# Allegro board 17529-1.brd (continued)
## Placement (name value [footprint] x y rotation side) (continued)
L2102  HCB1608KF-601T10-GP  [L603H38]  191.39 122.81 90 top
L2701  MHC1608S800QBP-GP  [L603H38]  76.33 232.16 90 top
L2702  MHC1608S800QBP-GP  [L603H38]  54.36 225.55 90 top
L2703  MHC1608S800QBP-GP  [L603H38]  54.36 224.28 90 top
L3001  MCB1005S121FBP-GP  [L402H24]  8.95 22.73 270 top
L3002  MCB1005S121FBP-GP  [L402H24]  9.03 25.35 270 top
L3003  MCB1005S121FBP-GP  [L402H24]  18.35 18.29 270 top
L3004  MCB1005S121FBP-GP  [L402H24]  18.41 21.34 270 top
L3005  MCB1005S121FBP-GP  [L402H24]  16 30.2 0 top
L3006  MCB1005S121FBP-GP  [L402H24]  14.99 30.2 0 top
L5301  IND-100UH-40-GP  [L6060-6018H186]  197.31 8.41 0 top
L5901  MHC1608S600QBP-GP  [L603H38]  67.39 27.25 0 top
L5902  MHC1608S600QBP-GP  [L603H38]  55.5 17.65 0 top
L5903  BLM18BB470SN1D-GP  [L1608-UH38]  65.1 15.37 0 top
L5904  BLM18BB470SN1D-GP  [L1608-UH38]  62.79 15.49 0 top
L5905  BLM18BB470SN1D-GP  [L1608-UH38]  60.58 15.49 0 top
L9501  MHC1608S601LBP-GP  [L603H38]  203.66 44.53 270 top
L9502  MHC1608S601LBP-GP  [L603H38]  190.6 58.9 0 top
L9503  MHC1608S601LBP-GP  [L603H38]  193.17 69.7 270 top
L9504  MHC1608S601LBP-GP  [L603H38]  192.43 67.72 0 top
LED1  LED-W-130-GP  [LED3640AK-1H160]  27.14 247.83 90 top
LPC1  ACES-CON14-5-GP  [87212-1400N]  228.02 99.49 180 top
NGFF1  SKT-NGFF75P-91-GP  [AS0BC21-S40BE-7H]  207 197 90 top
NGFF2  SKT-NGFF75P-90-GP-U  [AS0BC21-S85BM-7H]  144.86 130.9 0 top
NOREF  *  [unnamed]  46.41 22.81 0 top
NOREF#2  *  [unnamed]  234.7 183.44 0 top
NOREF#3  *  [unnamed]  119.58 67.16 0 top
NOREF#4  -  [#2]  0 253.23 0 top
NOREF#5  -  [#2]  6.2 268.6 180 top
NOREF#6  -  [#2]  173.48 143.38 0 top
NOREF#7  -  [unnamed]  11.58 254.45 0 top
NOREF#8  *  [unnamed]  146.1 95.15 0 top
NOREF#9  -  [unnamed]  116.41 149.38 0 top
NOREF#10  -  [#2]  174.02 160.27 0 top
NOREF#11  -  [unnamed]  144.86 103.3 0 top
NOREF#12  -  [unnamed]  230.38 3.81 0 top
NOREF#13  -  [unnamed]  41.41 74.38 0 top
NOREF#14  *  [unnamed]  238.3 3.2 0 top
NOREF#15  -  [#2]  237.8 224.8 0 top
NOREF#16  *  [unnamed]  238.63 226.95 0 top
NOREF#17  -  [unnamed]  241.05 229.62 0 top
NOREF#18  -  [unnamed]  41.41 149.38 0 top
NOREF#19  -  [#2]  -45.72 10.16 0 top
NOREF#20  -  [#2]  0 0 0 top
NOREF#21  *  [unnamed]  28.45 131.01 0 top
NOREF#22  -  [#2]  173.86 137.16 0 top
NOREF#23  *  [unnamed]  17.91 246 0 top
NOREF#24  -  [unnamed]  116.41 74.38 0 top
NOREF#25  -  [unnamed]  144.86 53.3 0 top
NOREF#26  *  [unnamed]  112.19 30.45 0 top
NOREF#27  -  [unnamed]  240.3 251.83 0 top
NOREF#28  -  [unnamed]  232.42 238.95 0 top
NOREF#29  -  [#2]  0 0 0 top
NOREF#30  -  [unnamed]  3.7 241.57 0 top
NOREF#31  -  [unnamed]  21.59 247.01 0 top
NOREF#32  -  [#2]  9.91 146.86 0 top
NOREF#33  -  [#2]  244 0 90 top
NOREF#34  *  [unnamed]  238.63 226.95 180 bottom
NOREF#35  *  [unnamed]  17.91 246 180 bottom
NOREF#36  *  [unnamed]  238.3 3.2 180 bottom
PC1034  SC22U6D3V5MX-2DLGP  [C805H54]  70.61 114.43 90 top
PC1035  SC47U6D3V5MX-1DL-GP  [C805H54]  38.73 90.93 180 top
PC1036  SC22U6D3V5MX-2DLGP  [C805H54]  69.77 108.1 180 top
PC1037  SC22U6D3V5MX-2DLGP  [C805H54]  71.94 108.1 180 top
PC1038  SC22U6D3V5MX-2DLGP  [C805H54]  71.94 111.68 180 top
PC1039  SC22U6D3V5MX-2DLGP  [C805H54]  74.1 111.68 180 top
PC1040  SC22U6D3V5MX-2DLGP  [C805H54]  69.77 111.68 180 top
PC1041  SC47U6D3V5MX-1DL-GP  [C805H54]  38.68 99.01 180 top
PC1042  SC47U6D3V5MX-1DL-GP  [C805H54]  38.71 106.91 180 top
PC1043  SC47U6D3V5MX-1DL-GP  [C805H54]  38.61 83.19 0 top
PC1044  SC47U6D3V5MX-1DL-GP  [C805H54]  31.67 118.47 180 top
PC1045  SC47U6D3V5MX-1DL-GP  [C805H54]  33.66 118.47 180 top
PC1046  SC22U6D3V3MX-1-DL-GP  [C603H40]  86.41 109.14 270 top
PC1047  SC22U6D3V3MX-1-DL-GP  [C603H40]  74.14 115.01 0 top
PC1048  SC22U6D3V3MX-1-DL-GP  [C603H40]  72.97 115.01 0 top
PC1049  SC22U6D3V3MX-1-DL-GP  [C603H40]  83.59 116.15 0 top
PC1050  SC47U6D3V5MX-1DL-GP  [C805H54]  85.98 116.51 270 top
PC1051  SC47U6D3V5MX-1DL-GP  [C805H54]  85.98 114.58 270 top
PC1052  SC47U6D3V5MX-1DL-GP  [C805H54]  85.98 112.65 270 top
PC1053  SC47U6D3V5MX-1DL-GP  [C805H54]  85.98 110.72 270 top
PC1068  SC22U6D3V5MX-2DLGP  [C805H54]  70.61 116.51 90 top
PC4401  SC1U50V3KX-1-GP  [C603H36]  24.31 80.39 180 top
PC4402  SC2D2U10V3KX-1DLGP-U  [C603H36]  20.83 76.71 270 top
PC4403  SCD01U50V2KX-1DLGP  [C402H22]  18.54 78.49 180 top
PC4404  SC470P50V2KX-3DLGP  [C402H22]  29.03 72.47 270 top
PC4405  SC2200P50V2KX-2DLGP  [C402H22]  28.88 70.54 270 top
PC4406  SC33P50V2JN-3DLGP  [C402H22]  27.46 71.07 0 top
PC4407  SCD1U25V2KX-1-DL-GP  [C402H22]  24.77 60.33 0 top
PC4408  SCD1U25V2KX-1-DL-GP  [C402H22]  25.98 62.23 0 top
PC4409  SC1KP50V2KX-1DLGP  [C402H22]  29.46 75.82 180 top
PC4410  SCD1U25V2KX-1-DL-GP  [C402H22]  26.62 64.26 0 top
PC4411  SC3300P50V2KX-1DLGP  [C402H22]  27.51 75.82 0 top
PC4412  SCD1U25V2KX-1-DL-GP  [C402H22]  26.09 66.17 0 top
PC4413  SC220P50V2KX-3DLGP  [C402H22]  27.43 69.14 0 top
PC4414  SC470P50V2KX-3DLGP  [C402H22]  25.53 76.33 180 top
PC4415  SC1500P50V2KX-2-DL-GP  [C402H22]  28.32 69.14 0 top
PC4416  SC1KP50V2KX-1DLGP  [C402H22]  26.8 67.56 90 top
PC4417  SC470P50V2KX-3DLGP  [C402H22]  8.81 73.15 0 top
PC4418  SC2200P50V2KX-2DLGP  [C402H22]  12.57 71.09 90 top
PC4419  SC33P50V2JN-3DLGP  [C402H22]  12.57 72.01 90 top
PC4420  SCD1U25V2KX-1-DL-GP  [C402H22]  14.15 66.04 0 top
PC4421  SCD1U25V2KX-1-DL-GP  [C402H22]  12.95 63.5 0 top
PC4422  SC1KP50V2KX-1DLGP  [C402H22]  12.19 76.07 180 top
PC4423  SC3300P50V2KX-1DLGP  [C402H22]  14.22 76.07 0 top
PC4424  SC220P50V2KX-3DLGP  [C402H22]  11.94 69.7 0 top
PC4425  SC1500P50V2KX-2-DL-GP  [C402H22]  12.83 69.7 0 top
PC4426  SC470P50V2KX-3DLGP  [C402H22]  16.26 76.07 180 top
PC4427  SC1KP50V2KX-1DLGP  [C402H22]  13.46 68.2 270 top
PC4428  SCD1U25V2KX-1-DL-GP  [C402H22]  15.16 62.46 0 top
PC4429  SCD1U25V2KX-1-DL-GP  [C402H22]  22.23 60.33 0 top
PC4501  SC10U25V5KX-DL-GP  [C805H58]  51.51 46.08 180 top
PC4502  SC10U25V5KX-DL-GP  [C805H58]  53.54 46.08 180 top
PC4503  SCD1U50V3KX-DL-GP  [C603H35]  40.23 50.62 90 top
PC4504  SC1U50V3KX-1-GP  [C603H36]  38.48 45.29 270 top
PC4505  SC1500P50V2KX-2-DL-GP  [C402H22]  33.22 64.87 270 top
PC4506  SC10U25V5KX-DL-GP  [C805H58]  60.2 49.02 270 top
PC4507  SC10U25V5KX-DL-GP  [C805H58]  70.48 50.93 180 top
PC4508  SCD1U50V3KX-DL-GP  [C603H35]  58.55 55.27 90 top
PC4509  SC1U50V3KX-1-GP  [C603H36]  56.26 50.29 270 top
PC4510  SC1500P50V2KX-2-DL-GP  [C402H22]  53.34 69.6 270 top
PC4511  SC10U25V5KX-DL-GP  [C805H58]  79.45 51.97 180 top
PC4512  SC10U25V5KX-DL-GP  [C805H58]  88.52 51.69 180 top
PC4513  SCD1U50V3KX-DL-GP  [C603H35]  76.83 58.29 90 top
PC4514  SC1U50V3KX-1-GP  [C603H36]  74.88 53.06 270 top
PC4515  SC1500P50V2KX-2-DL-GP  [C402H22]  71.63 72.64 270 top
PC4516  SC10U25V5KX-DL-GP  [C805H58]  105.28 51.69 90 top
PC4517  SC10U25V5KX-DL-GP  [C805H58]  97.94 52.22 180 top
PC4518  SCD1U50V3KX-DL-GP  [C603H35]  95.38 58.8 90 top
PC4519  SC1U50V3KX-1-GP  [C603H36]  93.85 52.96 270 top
PC4520  SC1500P50V2KX-2-DL-GP  [C402H22]  90.17 73.15 270 top
PC4601  SC10U25V5KX-DL-GP  [C805H58]  11.43 89.15 90 top
PC4602  SC10U25V5KX-DL-GP  [C805H58]  11.43 91.19 90 top
PC4603  SCD1U50V3KX-DL-GP  [C603H35]  13.84 87.38 90 top
PC4604  SC1U50V3KX-1-GP  [C603H36]  12.32 82.04 270 top
PC4605  SC1500P50V2KX-2-DL-GP  [C402H22]  16.26 85.47 0 top
PC4606  SC10U25V5KX-DL-GP  [C805H58]  12.19 116.2 90 top
PC4607  SC10U25V5KX-DL-GP  [C805H58]  12.19 118.24 90 top
PC4608  SCD1U50V3KX-DL-GP  [C603H35]  15.88 128.57 90 top
PC4609  SC1U50V3KX-1-GP  [C603H36]  19 124.74 0 top
PC4610  SC1500P50V2KX-2-DL-GP  [C402H22]  26.57 122.48 180 top
PC4701  SC1U50V3KX-1-GP  [C603H36]  116.28 40.36 90 top
PC4702  SC10U25V5KX-DL-GP  [C805H58]  113.97 39.5 0 top
PC4703  SC10U25V5KX-DL-GP  [C805H58]  112.04 39.5 0 top
PC4704  SCD1U50V3KX-DL-GP  [C603H35]  118.95 38.53 270 top
PC4705  SC1U50V3KX-1-GP  [C603H36]  125.09 55.75 90 top
PC4706  SC1U50V3KX-1-GP  [C603H36]  122.05 37.97 90 top
PC4707  SC1500P50V2KX-2-DL-GP  [C402H22]  124.71 46.08 0 top
PC4708  SC18P50V2JN-1DLGP  [C402H22]  123.57 33.4 0 top
PC4801  SC10U10V5KX-2DLGP  [C805H50]  127 104.01 270 top
PC4802  SC10U10V5KX-2DLGP  [C805H50]  127 101.98 270 top
PC4803  SCD1U16V2KX-3DLGP  [C402H22]  126.36 105.54 270 top
PC4804  SC1U50V3KX-1-GP  [C603H36]  127.99 90.73 270 top
PC4805  SCD047U25V2KX-4-GP  [C402H22]  131.57 93.34 180 top
PC4806  SCD01U50V2KX-1DLGP  [C402H22]  127.74 91.87 270 top
PC4807  SC1KP50V2KX-1DLGP  [C402H22]  134.54 91.67 180 top
PC4808  SC22U6D3V5MX-2DLGP  [C805H54]  123.9 99.97 180 top
PC4809  SC22U6D3V5MX-2DLGP  [C805H54]  121.87 100 180 top
PC4810  SCD1U16V2KX-3DLGP  [C402H22]  120.4 100.2 180 top
PC4811  SCD047U25V2KX-4-GP  [C402H22]  135.51 93.6 0 top
PC4812  SC2200P50V2KX-2DLGP  [C402H22]  136.53 92.58 180 top
PC4901  SC10U25V5KX-DL-GP  [C805H58]  39.07 207.21 180 top
PC4902  SC10U25V5KX-DL-GP  [C805H58]  53.21 208.28 0 top
PC4903  SC10U25V5KX-DL-GP  [C805H58]  41.15 201.68 0 top
PC4904  SC10U25V5KX-DL-GP  [C805H58]  51.18 208.28 0 top
PC4905  SC10U25V5KX-DL-GP  [C805H58]  39.12 201.68 0 top
PC4906  SCD1U50V3KX-DL-GP  [C603H35]  33.66 195.83 90 top
PC4907  SCD1U50V3KX-DL-GP  [C603H35]  37.64 191.74 90 top
PC4908  SCD1U50V3KX-DL-GP  [C603H35]  26.97 191.64 90 top
PC4909  SC1U50V3KX-1-GP  [C603H36]  80.64 216.28 180 top
PC4910  SC1U50V3KX-1-GP  [C603H36]  16.51 207.52 180 top
PC4911  SC1KP50V2KX-1DLGP  [C402H22]  56.26 207.65 270 top
PC4912  SC1KP50V2KX-1DLGP  [C402H22]  36.32 206.88 90 top
PC4913  SCD1U16V2KX-3DLGP  [C402H22]  29.51 196.24 180 top
PC4914  SC22P50V2JN-4DLGP  [C402H22]  33.73 186.36 180 top
PC4915  SC22P50V2JN-4DLGP  [C402H22]  28.45 186.44 180 top
PC4916  SC1U50V3KX-1-GP  [C603H36]  31.57 186.49 0 top
PC4917  SC1U50V3KX-1-GP  [C603H36]  31.55 196.65 180 top
PC4918  SCD22U10V2KX-2-GP  [C402H22]  36.58 189.61 90 top
PC4919  SCD22U10V2KX-2-GP  [C402H22]  27.48 190.58 270 top
PC5001  SC1U50V3KX-1-GP  [C603H36]  55.04 189.31 90 top
PC5002  SC1U50V3KX-1-GP  [C603H36]  55.04 190.58 90 top
PC5003  SC1U50V3KX-1-GP  [C603H36]  63.63 193.68 0 top
PC5004  SC10U25V5KX-DL-GP  [C805H58]  59.94 193.42 0 top
PC5005  SC10U25V5KX-DL-GP  [C805H58]  61.98 198.12 180 top
PC5006  SC10U25V5KX-DL-GP  [C805H58]  61.98 193.42 0 top
PC5007  SC10U25V5KX-DL-GP  [C805H58]  59.94 198.12 180 top
PC5008  SCD1U50V3KX-DL-GP  [C603H35]  52.58 195.96 0 top
PC5009  SC10U10V5KX-2DLGP  [C805H50]  48.9 196.6 180 top
PC5010  SC1U50V3KX-1-GP  [C603H36]  92.38 191.11 90 top
PC5011  SC10U10V5KX-2DLGP  [C805H50]  44.32 191.39 270 top
PC5012  SC10U10V5KX-2DLGP  [C805H50]  44.32 193.32 270 top
PC5013  SC18P50V2JN-1DLGP  [C402H22]  46.86 188.59 0 top
PC5014  SC1500P50V2KX-2-DL-GP  [C402H22]  65.89 192.63 270 top
PC5015  SCD047U25V2KX-4-GP  [C402H22]  44.45 189.99 270 top
PC5101  SC1U50V3KX-1-GP  [C603H36]  234.59 145.69 270 top
PC5102  SC10U25V5KX-DL-GP  [C805H58]  234.16 144.15 270 top
PC5103  SC10U25V5KX-DL-GP  [C805H58]  237.69 137.77 90 top
PC5104  SC10U25V5KX-DL-GP  [C805H58]  237.69 135.84 90 top
PC5105  SC10U25V5KX-DL-GP  [C805H58]  234.16 142.19 270 top
PC5106  SCD1U50V3KX-DL-GP  [C603H35]  234.45 147.64 90 top
PC5107  SC1U50V3KX-1-GP  [C603H36]  225.32 128.14 180 top
PC5108  SC18P50V2JN-1DLGP  [C402H22]  230.89 154.05 90 top
PC5109  SC1U50V3KX-1-GP  [C603H36]  230.59 149.07 270 top
PC5110  SC1500P50V2KX-2-DL-GP  [C402H22]  227.48 143.21 0 top
PC5201  SC10U10V5KX-2DLGP  [C805H50]  150.04 194.51 90 top
PC5202  SC1U50V3KX-1-GP  [C603H36]  143.26 191.9 180 top
PC5203  SC10U10V5KX-2DLGP  [C805H50]  154.94 193.55 180 top
PC5204  SC10U10V5KX-2DLGP  [C805H50]  152.91 193.55 180 top
PC5205  SCD1U16V2KX-3DLGP  [C402H22]  143 187.83 270 top
PC5206  SC150P50V2JN-3GP  [C402H22]  152.65 189.23 180 top
PG4501  GAP-CLOSE-PWR-3-GP  [GAP-CLOSE-PWR-3]  45.59 58.17 90 bottom
PG4502  GAP-CLOSE-PWR-3-GP  [GAP-CLOSE-PWR-3]  44.55 60.17 180 bottom
PG4503  GAP-CLOSE-PWR-3-GP  [GAP-CLOSE-PWR-3]  56.64 64.9 135 bottom
PG4504  GAP-CLOSE-PWR-3-GP  [GAP-CLOSE-PWR-3]  57.4 65.66 135 bottom
PG4505  GAP-CLOSE-PWR-3-GP  [GAP-CLOSE-PWR-3]  76.83 67.82 135 bottom
PG4506  GAP-CLOSE-PWR-3-GP  [GAP-CLOSE-PWR-3]  77.6 68.58 135 bottom
PG4507  GAP-CLOSE-PWR-3-GP  [GAP-CLOSE-PWR-3]  100.58 66.17 90 bottom
PG4508  GAP-CLOSE-PWR-3-GP  [GAP-CLOSE-PWR-3]  99.14 68.17 180 bottom
PG4601  GAP-CLOSE-PWR-3-GP  [GAP-CLOSE-PWR-3]  23.67 94.82 0 bottom
PG4602  GAP-CLOSE-PWR-3-GP  [GAP-CLOSE-PWR-3]  24.89 97.28 180 bottom
PG4603  GAP-CLOSE-PWR-3-GP  [GAP-CLOSE-PWR-3]  23.55 109.17 0 bottom
PG4604  GAP-CLOSE-PWR-3-GP  [GAP-CLOSE-PWR-3]  25.15 110.46 180 bottom
PG4701  GAP-CLOSE-PWR-3-GP  [GAP-CLOSE-PWR-3]  124.33 54.36 270 top
PG4901  GAP-CLOSE-PWR-3-GP  [GAP-CLOSE-PWR-3]  16.51 193.8 90 top
PG4902  GAP-CLOSE-PWR-3-GP  [GAP-CLOSE-PWR-3]  83.69 204.34 90 top
PG4903  GAP-CLOSE-PWR-2U-GP  [GAP-CLOSE-PWR-2U]  30.45 196.24 90 top
PG5005  GAP-CLOSE-PWR-3-GP  [GAP-CLOSE-PWR-3]  43.94 194.94 0 top
PG5006  GAP-CLOSE-PWR-3-GP  [GAP-CLOSE-PWR-3]  43.94 195.71 0 top
PL4501  COIL-D36UH-19-GP  [RT-D6D3-1D4-103065H394]  46.23 58.8 270 top
PL4502  COIL-D36UH-19-GP  [RT-D6D3-1D4-103065H394]  64.52 63.5 270 top
PL4503  COIL-D36UH-19-GP  [RT-D6D3-1D4-103065H394]  82.8 66.55 270 top
PL4504  COIL-D36UH-19-GP  [RT-D6D3-1D4-103065H394]  101.35 67.06 270 top
PL4601  COIL-D36UH-19-GP  [RT-D6D3-1D4-103065H394]  24.26 96.65 180 top
PL4602  COIL-D36UH-19-GP  [RT-D6D3-1D4-103065H394]  24.26 110.87 180 top
PL4701  IND-D47UH-22-GP-U  [L7066-1830-UH119]  119.76 51.82 180 top
PL4901  IND-2D2UH-356-GP  [RT-D6D6-6D6-108108H426]  68.96 209.17 180 top
PL4902  IND-2D2UH-356-GP  [RT-D6D6-6D6-108108H426]  23.52 207.54 180 top
PL4903  MHC2012S800UBP-GP  [L805H44]  50.42 213.82 0 top
PL4904  MHC2012S800UBP-GP  [L805H44]  47.19 213.84 0 top
PL4905  MHC2012S800UBP-GP  [L805H44]  44.27 213.89 0 top
PL5001  COIL-1D2UH-50-GP  [RT-D6D4-1D9-103072H394]  78.59 195.12 180 top
PL5002  MHC2012S800UBP-GP  [L805H44]  57.18 197.26 270 top
PL5003  MHC2012S800UBP-GP  [L805H44]  57.18 195.3 270 top
PL5101  IND-1D5UH-52-GP  [L115100-2030H158]  231.55 128.14 0 top
PL5104  MHC2012S800UBP-GP  [L805H44]  237.72 145.47 90 top
PL5105  MHC2012S800UBP-GP  [L805H44]  237.72 143.51 90 top
PR4401  2D2R3-1-U-GP  [R603H22]  20.7 79.76 0 top
PR4402  1KR2F-3-GP  [R402H16]  17.53 78.49 0 top
PR4403  26K1R2F-2-GP  [R402H16]  18.16 61.47 0 top
PR4404  100R2F-L1-GP-U  [R402H14]  27.05 80.01 0 top
PR4405  45D3R2F-L-GP  [R402H16]  23.75 78.49 270 top
PR4406  75R2F-2-GP  [R402H16]  24.26 76.96 0 top
PR4407  47R2F-GP  [R402H16]  29.97 73.43 90 top
PR4408  4K02R2F-GP  [R402H16]  28.88 71.5 90 top
PR4409  1KR2F-3-GP  [R402H16]  27.43 73.03 0 top
PR4410  10R2F-L-GP  [R402H14]  26.04 79.12 180 top
PR4411  49D9R2F-GP  [R402H16]  23.24 76.96 180 top
PR4412  100KR2F-L1-GP  [R402H16]  25.78 60.33 0 top
PR4413  10KR2F-2-GP  [R402H16]  21.21 61.47 0 top
PR4414  6K98R2F-GP  [R402H16]  28.07 59.44 270 top
PR4415  100KR2F-L1-GP  [R402H16]  25.02 62.23 0 top
PR4416  100R2F-L1-GP-U  [R402H14]  31.5 75.82 180 top
PR4417  6K98R2F-GP  [R402H16]  28.07 61.59 270 top
PR4418  0R0402-PAD-2-GP  [0R0402-PAD-1]  30.48 75.82 0 top
PR4419  100KR2F-L1-GP  [R402H16]  25.65 64.26 0 top
PR4420  3KR2F-GP  [R402H16]  28.45 75.82 0 top
PR4421  6K98R2F-GP  [R402H16]  28.07 63.88 270 top
PR4422  100KR2F-L1-GP  [R402H16]  27.03 66.17 0 top
PR4423  100R2F-L1-GP-U  [R402H14]  28.07 77.34 270 top
PR4424  10KR2F-2-GP  [R402H16]  20.19 61.47 0 top
PR4425  6K98R2F-GP  [R402H16]  29.67 66.67 270 top
PR4426  100KR2F-L1-GP  [R402H16]  29.97 59.44 270 top
PR4427  100KR2F-L1-GP  [R402H16]  29.46 69.14 0 top
PR4428  300KR2F-GP  [R402H16]  30.61 68.58 0 top
PR4429  100KR2F-L1-GP  [R402H16]  30.45 60.88 180 top
PR4430  30KR2F-GP  [R402H16]  26.54 76.33 180 top
PR4431  NTC-100K-11-GP-U  [NTC-402H24-U]  42.57 65.51 270 top
PR4432  100KR2F-L1-GP  [R402H16]  30.38 63.7 180 top
PR4433  35K7R2F-GP  [R402H16]  26.42 69.22 180 top
PR4434  100KR2F-L1-GP  [R402H16]  31.17 66.12 180 top
PR4435  10R2F-L-GP  [R402H14]  28.07 58.42 270 top
PR4436  10R2F-L-GP  [R402H14]  28.14 60.55 270 top
PR4437  10R2F-L-GP  [R402H14]  28.07 62.74 270 top
PR4438  10R2F-L-GP  [R402H14]  29.59 65.66 270 top
PR4439  47R2F-GP  [R402H16]  9.65 74.68 270 top
PR4440  4K02R2F-GP  [R402H16]  10.92 72.26 0 top
PR4441  10KR2F-2-GP  [R402H16]  17.14 61.47 0 top
PR4442  1KR2F-3-GP  [R402H16]  9.83 73.15 0 top
PR4443  100KR2F-L1-GP  [R402H16]  13.21 66.04 0 top
PR4444  6K98R2F-GP  [R402H16]  11.18 67.18 0 top
PR4445  100R2F-L1-GP-U  [R402H14]  15.75 78.61 270 top
PR4446  100KR2F-L1-GP  [R402H16]  11.94 63.5 0 top
PR4447  0R0402-PAD-2-GP  [0R0402-PAD-1]  11.18 76.07 0 top
PR4448  6K98R2F-GP  [R402H16]  10.41 63.63 90 top
PR4449  68K1R3F-1-GP  [R603]  10.03 66.93 180 top
PR4450  3K6R2F-GP  [R402H16]  13.21 76.07 0 top
PR4451  100KR2F-L1-GP  [R402H16]  9.53 70.74 270 top
PR4452  294KR2F-1-GP  [R402H16]  9.53 69.22 0 top
PR4453  68K1R3F-1-GP  [R603]  8.76 64.26 0 top
PR4454  100R2F-L1-GP-U  [R402H14]  15.75 77.6 90 top
PR4455  NTC-100K-11-GP-U  [NTC-402H24-U]  21.08 101.47 90 top
PR4456  133KR2F-GP  [R402H16]  19.18 61.47 0 top
PR4457  24K9R2F-L-GP  [R402H16]  13.84 69.72 180 top
PR4458  42K2R2F-L-GP  [R402H16]  15.24 76.07 180 top
PR4459  10R2F-L-GP  [R402H14]  10.54 65.02 90 top
PR4460  10R2F-L-GP  [R402H14]  12.7 61.98 270 top
PR4461  75R2F-2-GP  [R402H16]  17.65 75.95 0 top
PR4462  2KR2F-3-GP  [R402H16]  21.08 77.85 90 top
PR4463  499R2F-2-GP  [R402H16]  14.15 62.46 0 top
PR4464  499R2F-2-GP  [R402H16]  23.24 60.33 0 top
PR4465  47K5R2F-GP  [R402H16]  16.13 61.47 0 top
PR4466  NTC-100K-11-GP-U  [NTC-402H24-U]  43.28 44.78 180 top
PR4467  38K3R2F-GP  [R402H16]  14.61 60.96 90 top
PR4468  NTC-100K-11-GP-U  [NTC-402H24-U]  14.61 99.57 90 top
PR4469  38K3R2F-GP  [R402H16]  22.86 58.8 270 top
PR4470  2D2R3-1-U-GP  [R603H22]  21.97 79.76 0 top
PR4471  20KR2F-L-GP  [R402H16]  19.56 78.49 180 top
PR4501  2D2R5F-2-GP  [R805H24]  37.08 49.99 90 top
PR4502  2D2R5F-2-GP  [R805H24]  36.14 44.09 180 top
PR4503  10KR2J-3-GP  [R402H16]  42.8 51.56 180 top
PR4504  1R5J-2-GP  [R805H24]  42.82 48.59 180 top
PR4505  2D2R5F-2-GP  [R805H24]  36.12 65.41 270 top
PR4506  51R2F-2-GP  [R402H16]  34.87 47.07 90 top
PR4507  2D2R5F-2-GP  [R805H24]  55.42 54.94 90 top
PR4508  2D2R5F-2-GP  [R805H24]  55.58 46.08 180 top
PR4509  10KR2J-3-GP  [R402H16]  61.09 56.26 180 top
PR4510  1R5J-2-GP  [R805H24]  61.09 53.47 180 top
PR4511  2D2R5F-2-GP  [R805H24]  56.13 70.1 270 top
PR4512  51R2F-2-GP  [R402H16]  53.49 50.9 90 top
PR4513  2D2R5F-2-GP  [R805H24]  75.18 51.44 270 top
PR4514  2D2R5F-2-GP  [R805H24]  73.66 57.91 90 top
PR4515  10KR2J-3-GP  [R402H16]  79.38 59.31 180 top
PR4516  1R5J-2-GP  [R805H24]  79.4 56.52 180 top
PR4517  2D2R5F-2-GP  [R805H24]  74.42 73.15 270 top
PR4518  51R2F-2-GP  [R402H16]  71.5 54.03 90 top
PR4519  2D2R5F-2-GP  [R805H24]  91.44 51.69 180 top
PR4520  2D2R5F-2-GP  [R805H24]  92.2 58.42 90 top
PR4521  10KR2J-3-GP  [R402H16]  97.92 59.82 180 top
PR4522  1R5J-2-GP  [R805H24]  97.92 57.02 180 top
PR4523  2D2R5F-2-GP  [R805H24]  93.01 73.66 270 top
PR4524  51R2F-2-GP  [R402H16]  89.87 55.19 90 top
PR4601  2D2R5F-2-GP  [R805H24]  10.49 87.07 90 top
PR4602  2D2R5F-2-GP  [R805H24]  8.89 82.55 90 top
PR4603  10KR2J-3-GP  [R402H16]  17.02 99.44 90 top
PR4604  1R5J-2-GP  [R805H24]  17.02 101.85 0 top
PR4605  2D2R5F-2-GP  [R805H24]  16.26 88.27 0 top
PR4606  51R2F-2-GP  [R402H16]  8.79 84.1 90 top
PR4607  2D2R5F-2-GP  [R805H24]  17.91 121.54 180 top
PR4608  2D2R5F-2-GP  [R805H24]  14.3 125.25 180 top
PR4609  10KR2J-3-GP  [R402H16]  17.91 115.7 90 top
PR4610  1R5J-2-GP  [R805H24]  16 116.97 0 top
PR4611  2D2R5F-2-GP  [R805H24]  26.54 118.62 180 top
PR4612  51R2F-2-GP  [R402H16]  14.4 122.3 90 top
PR4701  GAP-CLOSE-PWR-3-GP  [GAP-CLOSE-PWR-3]  110.36 44.07 180 top
PR4702  GAP-CLOSE-PWR-3-GP  [GAP-CLOSE-PWR-3]  110.36 43.31 180 top
PR4703  GAP-CLOSE-PWR-3-GP  [GAP-CLOSE-PWR-3]  110.36 42.55 180 top
PR4704  GAP-CLOSE-PWR-3-GP  [GAP-CLOSE-PWR-3]  110.36 41.78 180 top
PR4705  GAP-CLOSE-PWR-3-GP  [GAP-CLOSE-PWR-3]  110.36 41.02 180 top
PR4706  GAP-CLOSE-PWR-3-GP  [GAP-CLOSE-PWR-3]  110.36 40.26 180 top
PR4707  2D2R5J-1-GP  [R805H24]  113.41 46.23 270 top
PR4708  40K2R2F-GP  [R402H16]  118.87 30.23 180 top
PR4709  2D2R5J-1-GP  [R805H24]  116.64 35.97 180 top
PR4710  10KR2J-3-GP  [R402H16]  114.94 47.75 270 top
PR4711  470KR2F-GP  [R402H16]  122.56 33.4 180 top
PR4712  2D2R5J-1-GP  [R805H24]  122.3 39.62 90 top
PR4713  2D2R5J-1-GP  [R805H24]  124.59 49.73 0 top
PR4714  4K87R2F-GP  [R402H16]  124.59 33.4 0 top
PR4715  10R2F-L-GP  [R402H14]  124.08 34.92 90 top
PR4716  10KR2F-2-GP  [R402H16]  125.6 33.4 180 top
PR4717  10R2F-L-GP  [R402H14]  126.11 34.92 90 top
PR4801  GAP-CLOSE-PWR-3-GP  [GAP-CLOSE-PWR-3]  127.86 105.79 90 top
PR4802  GAP-CLOSE-PWR-3-GP  [GAP-CLOSE-PWR-3]  128.63 105.79 90 top
PR4803  GAP-CLOSE-PWR-3-GP  [GAP-CLOSE-PWR-3]  129.39 105.79 90 top
PR4804  GAP-CLOSE-PWR-3-GP  [GAP-CLOSE-PWR-3]  130.15 105.79 90 top
PR4805  GAP-CLOSE-PWR-3-GP  [GAP-CLOSE-PWR-3]  133.2 105.79 90 top
PR4806  GAP-CLOSE-PWR-3-GP  [GAP-CLOSE-PWR-3]  130.91 105.79 90 top
PR4807  GAP-CLOSE-PWR-3-GP  [GAP-CLOSE-PWR-3]  132.44 105.79 90 top
PR4808  10R2F-L-GP  [R402H14]  129.57 86.84 270 top
PR4809  GAP-CLOSE-PWR-3-GP  [GAP-CLOSE-PWR-3]  131.67 105.79 90 top
PR4810  100R5J-4-GP  [R805H24]  129.03 93.34 90 top
PR4811  2K2R2F-GP  [R402H16]  135.51 91.69 180 top
PR4812  0R0402-PAD-2-GP  [0R0402-PAD-1]  136.53 96.52 180 top
PR4813  10R2F-L-GP  [R402H14]  135.51 95.63 0 top
PR4814  4K7R2F-GP  [R402H16]  136.53 94.61 0 top
PR4815  10R2F-L-GP  [R402H14]  136.53 98.55 180 top
PR4816  24KR2F-GP  [R402H16]  134.49 93.6 180 top
PR4901  GAP-CLOSE-PWR-3-GP  [GAP-CLOSE-PWR-3]  84.07 206.38 180 top
PR4902  GAP-CLOSE-PWR-3-GP  [GAP-CLOSE-PWR-3]  84.07 207.14 180 top
PR4903  GAP-CLOSE-PWR-3-GP  [GAP-CLOSE-PWR-3]  84.07 207.9 180 top
PR4904  GAP-CLOSE-PWR-3-GP  [GAP-CLOSE-PWR-3]  84.07 208.66 180 top
PR4905  GAP-CLOSE-PWR-3-GP  [GAP-CLOSE-PWR-3]  84.07 210.19 180 top
PR4906  GAP-CLOSE-PWR-3-GP  [GAP-CLOSE-PWR-3]  84.07 209.42 180 top
PR4908  GAP-CLOSE-PWR-3-GP  [GAP-CLOSE-PWR-3]  84.07 213.23 180 top
PR4910  GAP-CLOSE-PWR-3-GP  [GAP-CLOSE-PWR-3]  84.07 214 180 top
PR4912  GAP-CLOSE-PWR-3-GP  [GAP-CLOSE-PWR-3]  84.07 214.76 180 top
PR4914  GAP-CLOSE-PWR-3-GP  [GAP-CLOSE-PWR-3]  84.07 215.52 180 top
PR4916  GAP-CLOSE-PWR-3-GP  [GAP-CLOSE-PWR-3]  84.07 216.28 180 top
PR4918  GAP-CLOSE-PWR-3-GP  [GAP-CLOSE-PWR-3]  84.07 205.61 180 top
PR4920  GAP-CLOSE-PWR-3-GP  [GAP-CLOSE-PWR-3]  84.07 210.95 180 top
PR4922  GAP-CLOSE-PWR-3-GP  [GAP-CLOSE-PWR-3]  84.07 211.71 180 top
PR4924  GAP-CLOSE-PWR-3-GP  [GAP-CLOSE-PWR-3]  84.07 212.47 180 top
PR4925  GAP-CLOSE-PWR-3-GP  [GAP-CLOSE-PWR-3]  16.13 202.62 180 top
PR4927  GAP-CLOSE-PWR-3-GP  [GAP-CLOSE-PWR-3]  16.13 201.85 180 top
PR4929  GAP-CLOSE-PWR-3-GP  [GAP-CLOSE-PWR-3]  16.13 201.09 180 top
PR4932  2D2R5J-1-GP  [R805H24]  34.04 197.49 270 top
PR4933  GAP-CLOSE-PWR-3-GP  [GAP-CLOSE-PWR-3]  16.13 195.76 180 top
PR4934  GAP-CLOSE-PWR-3-GP  [GAP-CLOSE-PWR-3]  16.13 195 180 top
PR4936  GAP-CLOSE-PWR-3-GP  [GAP-CLOSE-PWR-3]  16.13 196.52 180 top
PR4937  GAP-CLOSE-PWR-3-GP  [GAP-CLOSE-PWR-3]  16.13 205.66 180 top
PR4938  GAP-CLOSE-PWR-3-GP  [GAP-CLOSE-PWR-3]  16.13 204.9 180 top
PR4939  GAP-CLOSE-PWR-3-GP  [GAP-CLOSE-PWR-3]  16.13 204.14 180 top
PR4940  GAP-CLOSE-PWR-3-GP  [GAP-CLOSE-PWR-3]  16.13 203.38 180 top
PR4941  2D2R5J-1-GP  [R805H24]  27.05 200.15 270 top
PR4942  2D2R5J-1-GP  [R805H24]  37.77 193.4 270 top
PR4943  2D2R5J-1-GP  [R805H24]  26.95 193.27 270 top
PR4944  2D2R5J-1-GP  [R805H24]  59.94 216.41 90 top
PR4945  GAP-CLOSE-PWR-3-GP  [GAP-CLOSE-PWR-3]  16.13 197.28 180 top
PR4946  GAP-CLOSE-PWR-3-GP  [GAP-CLOSE-PWR-3]  16.13 198.04 180 top
PR4947  GAP-CLOSE-PWR-3-GP  [GAP-CLOSE-PWR-3]  16.13 198.81 180 top
PR4948  GAP-CLOSE-PWR-3-GP  [GAP-CLOSE-PWR-3]  16.13 199.57 180 top
PR4949  GAP-CLOSE-PWR-3-GP  [GAP-CLOSE-PWR-3]  16.13 200.33 180 top
PR4950  2D2R5J-1-GP  [R805H24]  59.94 207.65 270 top
PR4951  2D2R5J-1-GP  [R805H24]  32.26 206.88 90 top
PR4952  78K7R2F-GP  [R402H16]  34.42 187.83 90 top
PR4953  62KR2F-GP  [R402H16]  27.05 187.32 270 top
PR4954  6K65R2F-GP  [R402H16]  34.72 186.36 180 top
PR4955  15K4R2F-GP  [R402H16]  29.46 186.44 180 top
PR4956  10KR2F-2-GP  [R402H16]  32.72 186.36 0 top
PR4957  10KR2F-2-GP  [R402H16]  30.48 186.44 0 top
PR4958  100KR2J-1-GP  [R402H16]  36.6 190.6 90 top
PR4959  10KR2J-3-GP  [R402H16]  36.58 187.58 270 top
PR4960  100KR2F-L1-GP  [R402H16]  27.46 188.52 90 top
PR4961  10KR2J-3-GP  [R402H16]  36.58 188.59 90 top
PR4962  28KR2F-GP  [R402H16]  27.48 189.59 270 top
PR5001  2D2R2F-GP  [R402H16]  54.66 188.11 270 top
PR5002  0R0603-PAD-2-GP-U  [0R0603-PAD-1-U]  55.04 191.82 90 top
PR5003  205KR2F-GP  [R402H16]  55.37 192.91 90 top
PR5004  10KR2J-3-GP  [R402H16]  72.9 200.79 0 top
PR5005  2D2R5J-1-GP  [R805H24]  70.61 201.17 270 top
PR5006  GAP-CLOSE-PWR-3-GP  [GAP-CLOSE-PWR-3]  82.17 189.61 270 top
PR5007  2D2R5J-1-GP  [R805H24]  50.93 196.22 180 top
PR5008  GAP-CLOSE-PWR-3-GP  [GAP-CLOSE-PWR-3]  82.93 189.61 270 top
PR5009  620KR2F-GP  [R402H16]  54.74 186.18 270 top
PR5010  GAP-CLOSE-PWR-3-GP  [GAP-CLOSE-PWR-3]  83.69 189.61 270 top
PR5011  GAP-CLOSE-PWR-3-GP  [GAP-CLOSE-PWR-3]  89.79 189.61 270 top
PR5012  GAP-CLOSE-PWR-3-GP  [GAP-CLOSE-PWR-3]  88.27 189.61 270 top
PR5013  GAP-CLOSE-PWR-3-GP  [GAP-CLOSE-PWR-3]  89.03 189.61 270 top
PR5014  0R0805-PAD-2-GP-U  [0R0805-PAD-1-U]  46.86 196.6 0 top
PR5015  GAP-CLOSE-PWR-3-GP  [GAP-CLOSE-PWR-3]  91.31 189.61 270 top
PR5016  2D2R5J-1-GP  [R805H24]  69.95 192.63 270 top
PR5017  GAP-CLOSE-PWR-3-GP  [GAP-CLOSE-PWR-3]  90.55 189.61 270 top
PR5018  GAP-CLOSE-PWR-3-GP  [GAP-CLOSE-PWR-3]  87.5 189.61 270 top
PR5019  0R0402-PAD-2-GP  [0R0402-PAD-1]  77.95 189.53 180 top
PR5020  GAP-CLOSE-PWR-3-GP  [GAP-CLOSE-PWR-3]  84.45 189.61 270 top
PR5021  GAP-CLOSE-PWR-3-GP  [GAP-CLOSE-PWR-3]  85.22 189.61 270 top
PR5022  GAP-CLOSE-PWR-3-GP  [GAP-CLOSE-PWR-3]  85.98 189.61 270 top
PR5023  GAP-CLOSE-PWR-3-GP  [GAP-CLOSE-PWR-3]  86.74 189.61 270 top
PR5024  15K8R2F-GP  [R402H16]  45.85 188.59 0 top
PR5025  20KR2F-L-GP  [R402H16]  48.13 187.58 0 top
PR5026  GAP-CLOSE-PWR-3-GP  [GAP-CLOSE-PWR-3]  92.08 189.61 270 top
PR5027  GAP-CLOSE-PWR-3-GP  [GAP-CLOSE-PWR-3]  81.41 189.61 270 top
PR5028  GAP-CLOSE-PWR-3-GP  [GAP-CLOSE-PWR-3]  80.64 189.61 270 top
PR5029  GAP-CLOSE-PWR-3-GP  [GAP-CLOSE-PWR-3]  79.88 189.61 270 top
PR5030  GAP-CLOSE-PWR-3-GP  [GAP-CLOSE-PWR-3]  79.12 189.61 270 top
PR5107  10KR2J-3-GP  [R402H16]  235.48 156.62 0 top
PR5108  2D2R5J-1-GP  [R805H24]  238.15 132.97 180 top
PR5109  10KR2J-3-GP  [R402H16]  238.15 129.31 0 top
PR5110  2D2R5J-1-GP  [R805H24]  237.04 149.19 180 top
PR5111  56KR2F-GP  [R402H16]  234.36 156.62 180 top
PR5112  470KR2F-GP  [R402H16]  230.28 152.43 0 top
PR5113  2D2R5J-1-GP  [R805H24]  229.74 143.21 270 top
PR5114  4K87R2F-GP  [R402H16]  230.81 155.12 90 top
PR5115  2D2R5J-1-GP  [R805H24]  229.84 147.5 270 top
PR5116  10KR2F-2-GP  [R402H16]  231.23 156.64 180 top
PR5117  GAP-CLOSE-PWR-3-GP  [GAP-CLOSE-PWR-3]  225.32 123.57 180 top
PR5118  GAP-CLOSE-PWR-3-GP  [GAP-CLOSE-PWR-3]  225.32 122.81 180 top
PR5119  GAP-CLOSE-PWR-3-GP  [GAP-CLOSE-PWR-3]  225.32 124.33 180 top
PR5120  GAP-CLOSE-PWR-3-GP  [GAP-CLOSE-PWR-3]  225.32 122.05 180 top
PR5121  GAP-CLOSE-PWR-3-GP  [GAP-CLOSE-PWR-3]  225.32 120.52 180 top
PR5122  GAP-CLOSE-PWR-3-GP  [GAP-CLOSE-PWR-3]  225.32 119.76 180 top
PR5123  GAP-CLOSE-PWR-3-GP  [GAP-CLOSE-PWR-3]  225.32 121.28 180 top
PR5124  GAP-CLOSE-PWR-3-GP  [GAP-CLOSE-PWR-3]  225.32 125.09 180 bottom
PR5125  GAP-CLOSE-PWR-3-GP  [GAP-CLOSE-PWR-3]  225.32 124.33 180 bottom
PR5126  GAP-CLOSE-PWR-3-GP  [GAP-CLOSE-PWR-3]  225.32 123.57 180 bottom
PR5127  GAP-CLOSE-PWR-3-GP  [GAP-CLOSE-PWR-3]  225.32 122.81 180 bottom
PR5128  GAP-CLOSE-PWR-3-GP  [GAP-CLOSE-PWR-3]  225.32 122.05 180 bottom
PR5129  GAP-CLOSE-PWR-3-GP  [GAP-CLOSE-PWR-3]  225.32 121.28 180 bottom
PR5130  GAP-CLOSE-PWR-3-GP  [GAP-CLOSE-PWR-3]  225.32 120.52 180 bottom
PR5131  GAP-CLOSE-PWR-3-GP  [GAP-CLOSE-PWR-3]  225.32 119.76 180 bottom
PR5132  GAP-CLOSE-PWR-3-GP  [GAP-CLOSE-PWR-3]  225.32 119 180 bottom
PR5133  GAP-CLOSE-PWR-3-GP  [GAP-CLOSE-PWR-3]  225.32 125.09 180 top
PR5134  GAP-CLOSE-PWR-3-GP  [GAP-CLOSE-PWR-3]  225.32 125.86 180 top
PR5135  GAP-CLOSE-PWR-3-GP  [GAP-CLOSE-PWR-3]  225.32 118.24 180 bottom
PR5201  0R0805-PAD-2-GP-U  [0R0805-PAD-1-U]  150.11 196.47 90 top
PR5202  10KR2F-2-GP  [R402H16]  143 189.87 90 top
PR5203  0R0805-PAD-2-GP-U  [0R0805-PAD-1-U]  155.19 188.34 0 top
PR5204  0R0402-PAD-2-GP  [0R0402-PAD-1]  143 188.82 90 top
PR5205  21K5R2F-GP  [R402H16]  153.67 189.23 0 top
PR5206  10KR2F-2-GP  [R402H16]  152.65 187.32 0 top
PT4501  E270U16VM-16-GP  [ECAP-138D8-UH355]  68.96 44.2 270 top
PT4502  E820U2D5VM-6-GP  [ECAP-100D6D3H375]  56.26 75.06 270 top
PT4503  E820U2D5VM-6-GP  [ECAP-100D6D3H375]  63.63 78.23 270 top
PT4504  E270U16VM-16-GP  [ECAP-138D8-UH355]  52.2 38.99 270 top
PT4505  E820U2D5VM-6-GP  [ECAP-100D6D3H375]  71.5 78.23 180 top
PT4506  E270U16VM-16-GP  [ECAP-138D8-UH355]  83.44 46.23 270 top
PT4507  E820U2D5VM-6-GP  [ECAP-100D6D3H375]  79.76 78.23 180 top
PT4508  E820U2D5VM-6-GP  [ECAP-100D6D3H375]  87.76 78.61 180 top
PT4601  E270U16VM-16-GP  [ECAP-138D8-UH355]  10.54 103.76 180 top
PT4602  E820U2D5VM-6-GP  [ECAP-100D6D3H375]  34.37 87.2 180 top
PT4603  E820U2D5VM-6-GP  [ECAP-100D6D3H375]  34.52 110.95 180 top
PT4604  E820U2D5VM-6-GP  [ECAP-100D6D3H375]  34.39 103.07 180 top
PT4605  E820U2D5VM-6-GP  [ECAP-100D6D3H375]  34.37 95.07 180 top
PT4701  E820U2D5VM-6-GP  [ECAP-100D6D3H375]  126.19 60.4 180 top
PT4702  E820U2D5VM-6-GP  [ECAP-100D6D3H375]  118.31 60.4 180 top
PT4801  E820U2D5VM-6-GP  [ECAP-100D6D3H375]  122.68 90.96 270 top
PT4901  E270U16VM-16-GP  [ECAP-138D8-UH355]  44.91 207.34 180 top
PT4902  SE220U6D3VM-3GP  [SE3116H241]  79.38 207.14 0 top
PT4903  SE220U6D3VM-3GP  [SE3116H241]  20.95 196.6 0 top
PT5001  E820U2D5VM-6-GP  [ECAP-100D6D3H375]  88.82 195 270 top
PT5101  E820U2D5VM-6-GP  [ECAP-100D6D3H375]  231.93 117.47 270 top
PU4401  NCP81220MNTXG-GP  [QFN52J6-G4D8-UH40]  19.81 69.85 0 top
PU4501  AONS36358-1-GP  [PPAK-8P-5262H40]  47.12 47.62 180 top
PU4502  NCP81258MNTBG-GP  [DFN8G2-G1309-UH40]  39.12 47.45 90 top
PU4503  AONS36356-GP  [PPAK-8P-5262H40]  38.73 61.09 270 top
PU4504  AONS36356-GP  [PPAK-8P-5262H40]  38.73 54.48 270 top
PU4505  AONS36358-1-GP  [PPAK-8P-5262H40]  65.41 52.32 180 top
PU4506  NCP81258MNTBG-GP  [DFN8G2-G1309-UH40]  56.52 52.45 90 top
PU4507  AONS36356-GP  [PPAK-8P-5262H40]  57.02 65.79 270 top
PU4508  AONS36356-GP  [PPAK-8P-5262H40]  57.02 59.18 270 top
PU4509  AONS36358-1-GP  [PPAK-8P-5262H40]  83.69 55.37 180 top
PU4510  NCP81258MNTBG-GP  [DFN8G2-G1309-UH40]  75.51 55.22 90 top
PU4511  AONS36356-GP  [PPAK-8P-5262H40]  75.31 68.83 270 top
PU4512  AONS36356-GP  [PPAK-8P-5262H40]  75.31 62.23 270 top
PU4513  AONS36358-1-GP  [PPAK-8P-5262H40]  102.23 55.88 180 top
PU4514  NCP81258MNTBG-GP  [DFN8G2-G1309-UH40]  94.17 55.21 90 top
PU4515  AONS36356-GP  [PPAK-8P-5262H40]  93.85 62.74 270 top
PU4516  AONS36356-GP  [PPAK-8P-5262H40]  93.85 69.34 270 top
PU4601  AONS36358-1-GP  [PPAK-8P-5262H40]  13.1 95.63 90 top
PU4602  NCP81258MNTBG-GP  [DFN8G2-G1309-UH40]  12.58 84.25 90 top
PU4603  AONS36356-GP  [PPAK-8P-5262H40]  20.57 89.15 0 top
PU4604  AONS36358-1-GP  [PPAK-8P-5262H40]  13.1 111.89 90 top
PU4605  NCP81258MNTBG-GP  [DFN8G2-G1309-UH40]  16.84 125.25 180 top
PU4606  AONS36356-GP  [PPAK-8P-5262H40]  22.17 118.39 180 top
PU4701  RT8237CZQW-2-GP  [DFN10G3-G265175H32]  119.89 34.54 180 top
PU4702  FDMS3600-02-RJK0215-COLAY-GP  [PPAK-8P-G5324H44-COLAY]  119.25 44.07 270 top
PU4801  APL5611ACI-TRG-GP  [SOT-6H58]  131.29 89.84 0 top
PU4802  AONS36358-1-GP  [PPAK-8P-5262H40]  130.05 97.66 270 top
PU4901  AONS36358-1-GP  [PPAK-8P-5262H40]  57.53 211.96 90 top
PU4902  RT6575DGQW-GP  [QFN20-G1D75H32]  32.05 191.77 180 top
PU4903  AONS36358-1-GP  [PPAK-8P-5262H40]  34.87 202.64 270 top
PU4904  AONS36356-GP  [PPAK-8P-5262H40]  59.18 203.33 270 top
PU4905  AONS36356-GP  [PPAK-8P-5262H40]  33.1 211.23 90 top
PU5001  RT8231AGQW-GP  [QFN20-G1D75H32]  49.91 191.06 90 top
PU5002  AONS36358-1-GP  [PPAK-8P-5262H40]  67.39 196.88 90 top
PU5003  AONS36356-GP  [PPAK-8P-5262H40]  69.16 188.39 270 top
PU5101  RT8237CZQW-2-GP  [DFN10G3-G265175H32]  233.96 151.76 0 top
PU5102  FDMS3600-02-RJK0215-COLAY-GP  [PPAK-8P-G5324H44-COLAY]  231.86 138.07 90 top
PU5201  APL5930KAI-TRG-1-GP  [SOIC8-G3530H63]  147.85 190.42 90 top
PWRSW1  SW-TACT-LED-5-GP-U  [SFNSDAA1542T-U]  13.48 243.2 180 top
Q801  AO3418L-GP  [SOT23DGS2D8H50]  129.67 119.76 270 top
Q802  2N7002KDW-1-GP  [SOT-363H44]  124.59 122.43 90 top
Q2001  LMBT3906LT1G-1-GP  [SOT23CBE2D4H44]  220.14 128.65 90 top
Q2401  MMDT3904-2-GP  [SOT-363-1H44]  206.3 72.93 270 top
Q2402  MMDT3904-2-GP  [SOT-363-1H44]  195 77.52 90 top
Q2403  LMBT3904LT1G-GP  [SOT23CBE2D4H44]  210.57 104.9 180 top
Q2404  LMBT3904LT1G-GP  [SOT23CBE2D4H44]  107.31 58.8 180 top
Q2405  MMDT3904-2-GP  [SOT-363-1H44]  197.87 73.66 90 top
Q2406  MMDT3904-2-GP  [SOT-363-1H44]  205.11 77.24 90 top
Q2407  2N7002K-2-GP  [SOT23DGS2D4H44]  209.12 78.64 90 top
Q2408  MMDT3904-2-GP  [SOT-363-1H44]  215.42 85.19 180 top
Q2409  LMBT3904LT1G-GP  [SOT23CBE2D4H44]  152.05 117.85 0 top
Q2701  LMBT3906LT1G-1-GP  [SOT23CBE2D4H44]  79.5 238.51 90 top
Q2702  LMBT3906LT1G-1-GP  [SOT23CBE2D4H44]  80.64 228.6 180 top
Q2703  LMBT3906LT1G-1-GP  [SOT23CBE2D4H44]  49.02 224.54 90 top
Q2704  LMBT3906LT1G-1-GP  [SOT23CBE2D4H44]  48.9 228.22 180 top
Q2901  MMDT3904-2-GP  [SOT-363-1H44]  74.42 240.03 90 top
Q3001  MMDT3904-2-GP  [SOT-363-1H44]  19.18 25.78 0 top
Q3801  MBT3904DW1T1G-2-GP  [SOT-363H44]  111 238.12 90 top
Q4001  LMBT3904LT1G-GP  [SOT23CBE2D4H44]  151.64 201.42 0 top
Q4002  MMDT3904-2-GP  [SOT-363-1H44]  148.21 201.55 180 top
Q4201  AONS36358-1-GP  [PPAK-8P-5262H40]  88.77 206.12 90 top
Q4202  MMDT3904-2-GP  [SOT-363-1H44]  179.2 216.79 180 top
Q4203  2N7002K-2-GP  [SOT23DGS2D4H44]  183.51 216.92 90 top
Q4204  MMDT3904-2-GP  [SOT-363-1H44]  171.83 217.81 180 top
Q4301  LMBT3904LT1G-GP  [SOT23CBE2D4H44]  217.42 215.65 0 top
Q5601  2N7002KDW-1-GP  [SOT-363H44]  22.48 21.79 0 top
Q5901  AO3418L-GP  [SOT23DGS2D8H50]  43.31 12.7 270 top
Q6301  2N7002KDW-1-GP  [SOT-363H44]  219.25 177.93 0 top
Q6401  2N7002KDW-1-GP  [SOT-363H44]  16.38 233.81 270 top
Q9101  2N7002K-2-GP  [SOT23DGS2D4H44]  178.05 205.99 0 top
R301  24D9R2F-L-GP  [R402H16]  86.22 107.19 0 top
R401  56D2R2F-GP  [R402H16]  32.84 80.29 180 top
R402  100R2F-L1-GP-U  [R402H14]  125.98 75.88 0 top
R403  100R2F-L1-GP-U  [R402H14]  32.46 81.94 90 top
R404  1KR2F-3-GP  [R402H16]  33.22 78.77 90 top
R405  220R2F-GP  [R402H16]  34.37 80.8 90 top
R407  0R0402-PAD-2-GP  [0R0402-PAD-1]  53.85 87.5 315 bottom
R408  0R0402-PAD-2-GP  [0R0402-PAD-1]  51.82 86.74 315 bottom
R409  499R2F-2-GP  [R402H16]  34.37 79.78 90 top
R410  0R0402-PAD-2-GP  [0R0402-PAD-1]  124.97 75.88 0 top
R411  0R0402-PAD-2-GP  [0R0402-PAD-1]  127.57 74.93 90 top
R412  0R0402-PAD-2-GP  [0R0402-PAD-1]  125.09 69.98 0 top
R413  10KR2J-3-GP  [R402H16]  10.29 189.1 90 top
R414  100KR2J-1-GP  [R402H16]  12.06 183.51 90 top
R415  51R2F-2-GP  [R402H16]  129.84 63.75 270 top
R416  10KR2J-3-GP  [R402H16]  10.16 183.51 90 top
R417  0R0402-PAD-2-GP  [0R0402-PAD-1]  128.14 73.47 0 top
R418  49D9R2F-GP  [R402H16]  84.7 106.81 270 top
R419  6K04R2F-GP  [R402H16]  125.6 108.08 270 top
R420  2K8R2F-GP  [R402H16]  124.08 107.57 0 top
R421  20R2F-GP  [R402H16]  129.67 78.42 180 top
R422  10KR2J-3-GP  [R402H16]  73.43 116.92 270 top
R423  1KR2J-1-GP  [R402H16]  124.82 79.2 0 top
R424  1KR2J-1-GP  [R402H16]  122.3 79.63 90 top
R425  1KR2J-1-GP  [R402H16]  123.77 79.2 0 top
R426  1KR2J-1-GP  [R402H16]  122.3 78.59 90 top
R601  2R2F-GP  [R402H16]  31.88 125.09 270 top
R602  24D9R2F-L-GP  [R402H16]  30.33 124.66 180 top
R701  24D9R2F-L-GP  [R402H16]  87.24 107.19 180 top
R702  20R2J-3-GP  [R402H16]  126.47 109.75 90 top
R801  0R0402-PAD-2-GP  [0R0402-PAD-1]  120.14 119.63 90 top
R802  49D9R2F-GP  [R402H16]  29.97 77.34 270 top
R803  0R3J-0-U-GP  [R603H22]  128.65 117.35 270 top
R804  47KR2J-2-GP  [R402H16]  155.88 205.59 0 top
R805  10KR2J-3-GP  [R402H16]  128.09 122.68 0 top
R806  100KR2J-1-GP  [R402H16]  127 122.68 0 top
R807  100KR2J-1-GP  [R402H16]  154.81 205.59 0 top
R808  4K7R2J-2-GP  [R402H16]  126.24 117.35 270 top
R809  0R0402-PAD-2-GP  [0R0402-PAD-1]  125.6 120.27 90 top
R810  100KR2J-1-GP  [R402H16]  122.25 122.68 0 top
R901  20R2F-GP  [R402H16]  133.6 79.44 180 top
R902  0R0402-PAD-2-GP  [0R0402-PAD-1]  88.94 100.46 270 bottom
R903  0R0402-PAD-2-GP  [0R0402-PAD-1]  94.89 128.65 315 bottom
R1101  240R2F-1-GP  [R402H16]  88.65 183.64 0 top
R1102  0R2J-2-GP  [R402H16]  18.16 164.97 270 top
R1103  1KR2F-3-GP  [R402H16]  14.86 183.96 0 top
R1104  470R2J-2-GP  [R402H16]  74.7 184.4 180 top
R1105  0R0402-PAD-2-GP  [0R0402-PAD-1]  17.14 183.96 180 top
R1106  1KR2F-3-GP  [R402H16]  15.94 183.95 180 top
R1201  240R2F-1-GP  [R402H16]  89.66 183.64 0 top
R1202  0R2J-2-GP  [R402H16]  20.45 184.66 0 top
R1203  1KR2F-3-GP  [R402H16]  18.29 186.82 180 top
R1204  2R2F-GP  [R402H16]  21.72 186.82 0 top
R1205  0R0402-PAD-2-GP  [0R0402-PAD-1]  20.57 186.82 0 top
R1206  1KR2F-3-GP  [R402H16]  19.43 186.82 0 top
R1207  24D9R2F-L-GP  [R402H16]  23.75 186.82 180 top
R1502  10KR2J-3-GP  [R402H16]  195.07 164.69 180 top
R1503  8K2R2F-1-GP  [R402H16]  202.31 164.97 180 top
R1504  33R2J-2-GP  [R402H16]  213.41 111.2 90 top
R1505  10KR2J-3-GP  [R402H16]  197.1 43.31 270 top
R1506  10KR2J-3-GP  [R402H16]  153.42 39.24 0 top
R1507  1MR2J-1-GP  [R402H16]  216.15 176.15 90 top
R1508  10KR2J-3-GP  [R402H16]  218.03 106.65 90 top
R1509  10KR2J-3-GP  [R402H16]  208.86 118.39 270 top
R1511  47KR2J-2-GP  [R402H16]  211.86 124.89 270 top
R1512  150R2F-1-GP  [R402H16]  212.22 129.41 0 top
R1513  100R2F-L1-GP-U  [R402H14]  187.1 140.61 180 top
R1514  200R2F-L-GP  [R402H16]  213.36 129.41 0 top
R1515  100KR2J-1-GP  [R402H16]  193.29 183.51 270 top
R1516  100KR2J-1-GP  [R402H16]  211.81 112.55 270 top
R1517  33R2J-2-GP  [R402H16]  214.55 119.48 270 top
R1518  22R2J-2-GP  [R402H16]  219.94 192.68 270 top
R1519  33R2J-2-GP  [R402H16]  214.4 121.97 180 top
R1520  22R2J-2-GP  [R402H16]  224.61 195.91 270 top
R1521  20KR2F-L-GP  [R402H16]  214.1 125.65 90 top
R1522  10KR2J-3-GP  [R402H16]  213.08 120.07 0 top
R1601  10KR2J-3-GP  [R402H16]  209.19 167.74 180 top
R1602  10KR2J-3-GP  [R402H16]  204.22 165.51 0 top
R1603  10KR2J-3-GP  [R402H16]  207.72 166.85 90 top
R1604  10KR2J-3-GP  [R402H16]  207.06 165.81 90 top
R1605  10KR2J-3-GP  [R402H16]  200.96 164.97 180 top
R1609  113R2F-GP  [R402H16]  190.07 129.17 0 top
R1610  10KR2J-3-GP  [R402H16]  189.06 129.17 0 top
R1611  1KR2F-3-GP  [R402H16]  191.09 129.17 0 top
R1701  0R0402-PAD-2-GP  [0R0402-PAD-1]  191.21 167.79 0 top
R1702  0R0402-PAD-2-GP  [0R0402-PAD-1]  192.23 167.79 0 top
R1703  1KR2J-1-GP  [R402H16]  197.61 122.81 270 top
R1704  10KR2J-3-GP  [R402H16]  201.78 168.53 180 top
R1705  10KR2J-3-GP  [R402H16]  203.23 168.5 180 top
R1706  10KR2J-3-GP  [R402H16]  190.2 167.79 180 top
R1708  1KR2J-1-GP  [R402H16]  201.93 122.94 0 top
R1709  10KR2J-3-GP  [R402H16]  209.3 164.34 0 top
R1710  619R2F-L1-GP  [R402H16]  198.63 123.83 270 top
R1711  30R2J-1-GP  [R402H16]  202.59 124.82 0 top
R1712  10KR2J-3-GP  [R402H16]  200.08 209.68 90 top
R1713  10KR2J-3-GP  [R402H16]  188.42 169.27 270 top
R1714  10KR2J-3-GP  [R402H16]  190.35 169.24 90 top
R1801  10KR2J-3-GP  [R402H16]  220.5 144.7 0 top
R1802  60D4R2F-GP  [R402H16]  195 128.85 180 top
R1803  10KR2J-3-GP  [R402H16]  149.1 40.77 0 top
R1805  10KR2J-3-GP  [R402H16]  212.47 107.31 270 top
R1806  10KR2J-3-GP  [R402H16]  209.3 110.74 90 top
R1807  10KR2J-3-GP  [R402H16]  199.39 168.53 180 top
R1808  0R2J-2-GP  [R402H16]  197.94 167.08 90 top
R1809  10KR2J-3-GP  [R402H16]  200.43 168.53 180 top
R1810  10KR2J-3-GP  [R402H16]  197.03 168.55 180 top
R1811  10KR2J-3-GP  [R402H16]  198.07 168.55 180 top
R1812  200KR2J-L1-GP  [R402H16]  198.63 129.62 270 top
R1814  10MR3J-L1-GP  [R603H22]  217.38 166.03 270 top
R1815  0R0402-PAD-2-GP  [0R0402-PAD-1]  195.45 126.34 0 top
R1818  0R0402-PAD-2-GP  [0R0402-PAD-1]  214.25 185.67 0 top
R1822  0R0402-PAD-2-GP  [0R0402-PAD-1]  215.77 186.18 90 top
R1901  8K2R2F-1-GP  [R402H16]  204.22 163.02 180 top
R1902  10KR2J-3-GP  [R402H16]  193.7 167.54 90 top
R1904  10KR2J-3-GP  [R402H16]  184.4 174.37 90 top
R1906  2K2R2J-2-GP  [R402H16]  207.77 111 0 top
R1907  2K2R2J-2-GP  [R402H16]  206.76 111 0 top
R1908  2K2R2J-2-GP  [R402H16]  27.3 27.05 270 top
R1910  10KR2J-3-GP  [R402H16]  223.16 147.45 90 top
R1911  10KR2J-3-GP  [R402H16]  205.36 168.5 180 top
R1912  10KR2J-3-GP  [R402H16]  189.08 167.79 180 top
R1913  33R2J-2-GP  [R402H16]  225.27 153.42 90 top
R1914  22R2J-2-GP  [R402H16]  221.56 149.38 0 top
R1915  22R2J-2-GP  [R402H16]  220.5 149.38 0 top
R1916  22R2J-2-GP  [R402H16]  219.46 148.08 0 top
R1917  10KR2J-3-GP  [R402H16]  193.7 168.58 90 top
R1918  10KR2J-3-GP  [R402H16]  220.42 173.43 90 top
R1919  10KR2J-3-GP  [R402H16]  220.42 174.57 90 top
R1920  100KR2J-1-GP  [R402H16]  225.25 154.58 270 top
R2001  10KR2J-3-GP  [R402H16]  220.27 155.19 90 top
R2002  10KR2J-3-GP  [R402H16]  225.68 150.01 0 top
R2003  1KR2J-1-GP  [R402H16]  206.5 115.44 0 top
R2004  0R2J-2-GP  [R402H16]  216.72 150.94 90 top
R2006  0R0402-PAD-2-GP  [0R0402-PAD-1]  202.18 128.5 0 top
R2007  10KR2J-3-GP  [R402H16]  218.54 145.75 0 top
R2008  0R0402-PAD-2-GP  [0R0402-PAD-1]  196.32 118.72 0 top
R2009  499R2F-2-GP  [R402H16]  224.16 141.86 90 top
R2010  499R2F-2-GP  [R402H16]  224.16 136.09 90 top
R2011  51R2F-2-GP  [R402H16]  201.07 118.77 90 top
R2012  1KR2J-1-GP  [R402H16]  225.81 143.89 90 top
R2013  1KR2J-1-GP  [R402H16]  224.16 142.88 90 top
R2014  1KR2J-1-GP  [R402H16]  219.46 163.45 90 top
R2015  10KR2J-3-GP  [R402H16]  217.65 155.83 90 top
R2016  10KR2J-3-GP  [R402H16]  219.89 158.67 180 top
R2017  33R2J-2-GP  [R402H16]  219.67 132.69 270 top
R2018  10KR2J-3-GP  [R402H16]  220.93 158.67 180 top
R2019  33R2J-2-GP  [R402H16]  219.67 131.51 270 top
R2020  33R2J-2-GP  [R402H16]  219.68 134.75 270 top
R2021  1K5R2F-2-GP  [R402H16]  197.36 118.72 0 top
R2022  33R2J-2-GP  [R402H16]  219.68 136.78 270 top
R2023  1KR2F-3-GP  [R402H16]  230.15 184.35 0 top
R2024  100R2F-L1-GP-U  [R402H14]  199.52 118.72 0 top
R2025  30R2J-1-GP  [R402H16]  206.07 119.13 180 top
R2026  51R2F-2-GP  [R402H16]  198.48 118.72 0 top
R2027  30R2J-1-GP  [R402H16]  207.14 119.13 180 top
R2028  51R2F-2-GP  [R402H16]  201.93 120.78 270 top
R2029  33R2J-2-GP  [R402H16]  219.72 138.94 270 top
R2030  1K5R2F-2-GP  [R402H16]  215.77 185.04 90 top
R2031  33R2J-2-GP  [R402H16]  219.72 137.87 270 top
R2032  33R2J-2-GP  [R402H16]  219.72 139.98 270 top
R2033  33R2J-2-GP  [R402H16]  219.73 141.03 270 top
R2034  0R0402-PAD-2-GP  [0R0402-PAD-1]  224.66 131.32 270 top
R2035  4K7R2J-2-GP  [R402H16]  235.03 177.19 0 top
R2036  0R0402-PAD-2-GP  [0R0402-PAD-1]  235.51 175.67 90 top
R2037  1KR2J-1-GP  [R402H16]  217.73 147.19 90 top
R2038  1KR2J-1-GP  [R402H16]  219.68 135.76 90 top
R2039  0R0402-PAD-2-GP  [0R0402-PAD-1]  223.52 130.3 90 top
R2040  30K1R2F-L-GP  [R402H16]  222.81 173.58 0 top
R2041  10KR2J-3-GP  [R402H16]  194.03 164.69 0 top
R2042  30K1R2F-L-GP  [R402H16]  217.68 174.65 0 top
R2043  4K7R2J-2-GP  [R402H16]  216.61 174.65 180 top
R2044  10KR2J-3-GP  [R402H16]  219.46 162.43 270 top
R2045  2K2R2J-2-GP  [R402H16]  213.04 114.85 0 top
R2046  0R2J-2-GP  [R402H16]  219.07 182.88 90 top
R2047  0R2J-2-GP  [R402H16]  219.07 183.9 90 top
R2048  0R0402-PAD-2-GP  [0R0402-PAD-1]  222.58 179.78 270 top
R2049  100KR2J-1-GP  [R402H16]  217.6 183.44 180 top
R2050  100KR2J-1-GP  [R402H16]  222.38 157.73 270 top
R2051  100KR2J-1-GP  [R402H16]  227.28 156.03 0 top
R2052  100KR2J-1-GP  [R402H16]  220.93 162.86 180 top
R2053  100KR2J-1-GP  [R402H16]  228.32 155.17 180 top
R2054  100KR2J-1-GP  [R402H16]  225.27 156.16 90 top
R2055  100KR2J-1-GP  [R402H16]  219.67 133.7 90 top
R2056  100KR2J-1-GP  [R402H16]  217.68 132.38 0 top
R2057  100KR2J-1-GP  [R402H16]  217.65 153.75 90 top
R2058  100KR2J-1-GP  [R402H16]  216.68 139.36 270 top
R2101  0R0603-PAD-2-GP-U  [0R0603-PAD-1-U]  203.58 143.38 90 bottom
R2102  0R3J-0-U-GP  [R603H22]  206.32 142.52 225 bottom
R2201  30D1R2F-L-GP  [R402H16]  203.33 119.25 0 top
R2301  4K7R2J-2-GP  [R402H16]  198.25 164.72 180 top
R2302  4K7R2J-2-GP  [R402H16]  206.43 168.5 180 top
R2303  10KR2J-3-GP  [R402H16]  211.81 122.22 90 top
R2304  20KR2J-L2-GP  [R402H16]  207.52 168.5 180 top
R2305  10KR2J-3-GP  [R402H16]  211.81 123.27 90 top
R2306  0R2J-2-GP  [R402H16]  220.17 108.58 90 top
R2307  4K7R2J-2-GP  [R402H16]  217.6 108.15 0 top
R2308  4K7R2J-2-GP  [R402H16]  219.02 144.27 90 top
R2309  20KR2J-L2-GP  [R402H16]  218.67 108.15 0 top
R2310  20KR2J-L2-GP  [R402H16]  212.47 127.89 90 top
R2311  1KR2J-1-GP  [R402H16]  217.53 144.27 180 top
R2312  10KR2J-3-GP  [R402H16]  214.83 124.36 90 top
R2313  20KR2J-L2-GP  [R402H16]  213.74 165.1 180 top
R2314  10KR2J-3-GP  [R402H16]  224.16 140.84 90 top
R2315  20KR2J-L2-GP  [R402H16]  209.17 113.16 90 top
R2316  20KR2J-L2-GP  [R402H16]  224.16 139.83 90 top
R2317  20KR2J-L2-GP  [R402H16]  213.74 166.62 270 top
R2318  1KR2J-1-GP  [R402H16]  217.66 154.77 90 top
R2319  4K7R2J-2-GP  [R402H16]  217.17 130.81 90 top
R2320  20KR2J-L2-GP  [R402H16]  216.92 129.29 0 top
R2321  4K7R2J-2-GP  [R402H16]  224.16 137.11 90 top
R2322  20KR2J-L2-GP  [R402H16]  196.16 164.69 180 top
R2323  20KR2J-L2-GP  [R402H16]  224.15 138.79 90 top
R2324  2K2R2J-2-GP  [R402H16]  27.69 25.53 0 top
R2325  1KR2J-1-GP  [R402H16]  211.46 164.85 90 top
R2326  4K7R2J-2-GP  [R402H16]  211.46 163.83 90 top
R2327  2K2R2J-2-GP  [R402H16]  205.61 111 0 top
R2328  4K7R2J-2-GP  [R402H16]  212.09 162.31 180 top
R2329  2K2R2J-2-GP  [R402H16]  208.86 119.46 90 top
R2330  20KR2J-L2-GP  [R402H16]  197.21 164.69 180 top
R2331  4K7R2J-2-GP  [R402H16]  215.26 163.83 90 top
R2332  4K7R2J-2-GP  [R402H16]  213.74 163.19 0 top
R2401  22R2J-2-GP  [R402H16]  202.69 105.03 90 top
R2402  8K2R2F-1-GP  [R402H16]  202.56 72.9 180 top
R2403  30KR2F-GP  [R402H16]  209.3 73.03 270 top
R2404  9K1R2F-1-GP  [R402H16]  197.56 78.21 0 top
R2405  30KR2F-GP  [R402H16]  192.43 78.71 0 top
R2406  100KR2J-1-GP  [R402H16]  202.69 106.55 180 top
R2407  22R2J-2-GP  [R402H16]  200.66 106.55 180 top
R2408  680R2F-GP  [R402H16]  203.71 72.95 180 top
R2409  6K8R2F-2-GP  [R402H16]  197.56 76.3 0 top
R2410  100KR2J-1-GP  [R402H16]  201.68 106.55 180 top
R2411  10KR2F-2-GP  [R402H16]  206.38 106.55 0 top
R2412  30KR2F-GP  [R402H16]  200.71 74.24 0 top
R2413  10KR2F-2-GP  [R402H16]  199.97 77.29 90 top
R2414  9K1R2F-1-GP  [R402H16]  208.15 75.18 270 top
R2415  2KR2F-3-GP  [R402H16]  202.06 77.85 90 top
R2416  2KR2F-3-GP  [R402H16]  204.37 106.55 180 top
R2417  9K1R2F-1-GP  [R402H16]  199.97 76.28 270 top
R2419  10KR2J-3-GP  [R402H16]  191.82 83.9 270 top
R2420  0R0402-PAD-2-GP  [0R0402-PAD-1]  210.59 82.85 270 top
R2421  10KR2J-3-GP  [R402H16]  192.15 96.39 270 top
R2422  0R0402-PAD-2-GP  [0R0402-PAD-1]  214.76 95.12 270 top
R2423  7K15R2F-L-GP  [R402H16]  208.15 76.33 90 top
R2424  33KR2F-GP  [R402H16]  202.06 76.71 270 top
R2425  10KR2J-3-GP  [R402H16]  192.15 98.42 270 top
R2426  0R0402-PAD-2-GP  [0R0402-PAD-1]  214.76 96.14 270 top
R2427  10KR2J-3-GP  [R402H16]  192.15 97.41 270 top
R2428  43D2R2F-GP  [R402H16]  214 99.19 270 top
R2429  160R2F-GP  [R402H16]  195.3 81.33 0 top
R2430  10KR2J-3-GP  [R402H16]  216.13 99.95 270 top
R2431  4K7R2J-2-GP  [R402H16]  216.79 104.65 180 top
R2432  10KR2J-3-GP  [R402H16]  192.63 86.94 270 top
R2433  33R2J-2-GP  [R402H16]  199.9 104.01 0 top
R2434  0R0402-PAD-2-GP  [0R0402-PAD-1]  195.83 103.63 90 top
R2435  10KR2J-3-GP  [R402H16]  207.39 81.81 90 top
R2436  1KR2J-1-GP  [R402H16]  192.18 93.47 270 top
R2437  1KR2J-1-GP  [R402H16]  192.2 91.34 270 top
R2438  0R0402-PAD-2-GP  [0R0402-PAD-1]  192.15 100.46 90 top
R2439  0R0402-PAD-2-GP  [0R0402-PAD-1]  196.85 105.59 0 top
R2442  20KR2J-L2-GP  [R402H16]  198.35 105.18 90 top
R2446  330KR2F-L-GP  [R402H16]  217.81 104.65 0 top
R2448  10KR2J-3-GP  [R402H16]  202.69 103.5 0 top
R2449  10KR2J-3-GP  [R402H16]  200.91 104.01 0 top
R2450  1KR2J-1-GP  [R402H16]  208.89 81.41 180 top
R2452  10KR2J-3-GP  [R402H16]  211.02 81.41 180 top
R2453  10KR2J-3-GP  [R402H16]  209.96 81.41 0 top
R2458  75R2J-1-GP  [R402H16]  215.26 103.89 90 top
R2459  1KR2J-1-GP  [R402H16]  192.2 92.38 270 top
R2460  100KR2F-L1-GP  [R402H16]  215.26 104.9 90 top
R2461  1KR2J-1-GP  [R402H16]  192.2 90.25 270 top
R2462  10KR2J-3-GP  [R402H16]  213.36 105.92 90 top
R2463  10KR2J-3-GP  [R402H16]  204.44 81.36 0 top
R2464  10KR2J-3-GP  [R402H16]  205.51 81.36 0 top
R2465  30KR2F-GP  [R402H16]  199.97 78.54 90 top
R2466  20KR2F-L-GP  [R402H16]  215.9 89.79 270 top
R2467  100KR2J-1-GP  [R402H16]  216.05 82.6 270 top
R2468  16KR2F-GP  [R402H16]  213.74 89.79 270 top
R2469  30KR2F-GP  [R402H16]  199.97 79.58 90 top
R2470  30KR2F-GP  [R402H16]  200.38 81.08 0 top
R2471  1K65R2F-GP  [R402H16]  215.9 87.76 90 top
R2472  6K8R2F-2-GP  [R402H16]  213.74 91.82 90 top
R2473  30KR2F-GP  [R402H16]  195.66 79.71 90 top
R2474  47KR2J-2-GP  [R402H16]  194.94 104.78 270 top
R2475  100KR2J-1-GP  [R402H16]  214.76 97.66 90 top
R2476  10KR2J-3-GP  [R402H16]  213.36 104.27 90 top
R2477  0R2J-2-GP  [R402H16]  217.04 68.83 180 top
R2478  10KR2J-3-GP  [R402H16]  217.04 70.74 180 top
R2501  1KR2J-1-GP  [R402H16]  186.26 190.63 0 top
R2502  1KR2J-1-GP  [R402H16]  192.25 191.03 270 top
R2503  0R0603-PAD-2-GP-U  [0R0603-PAD-1-U]  191.97 209.68 0 top
R2504  1K5R2F-2-GP  [R402H16]  130.86 216.69 90 top
R2505  45K3R2F-L-GP  [R402H16]  130.86 217.7 270 top
R2506  1KR2J-1-GP  [R402H16]  134.75 220.09 0 top
R2601  4K7R2J-2-GP  [R402H16]  14.35 133.48 0 top
R2602  20KR2J-L2-GP  [R402H16]  15.37 133.48 180 top
R2603  2K2R2J-2-GP  [R402H16]  16.64 131.95 270 top
R2604  8K2R2F-1-GP  [R402H16]  16.38 133.48 0 top
R2605  100R2F-L1-GP-U  [R402H14]  14.73 131.95 90 top
R2611  9K53R2F-GP  [R402H16]  106.71 62.64 270 top
R2612  0R2J-2-GP  [R402H16]  85.88 16.81 180 top
R2613  10K5R2F-GP  [R402H16]  87.93 14.05 90 top
